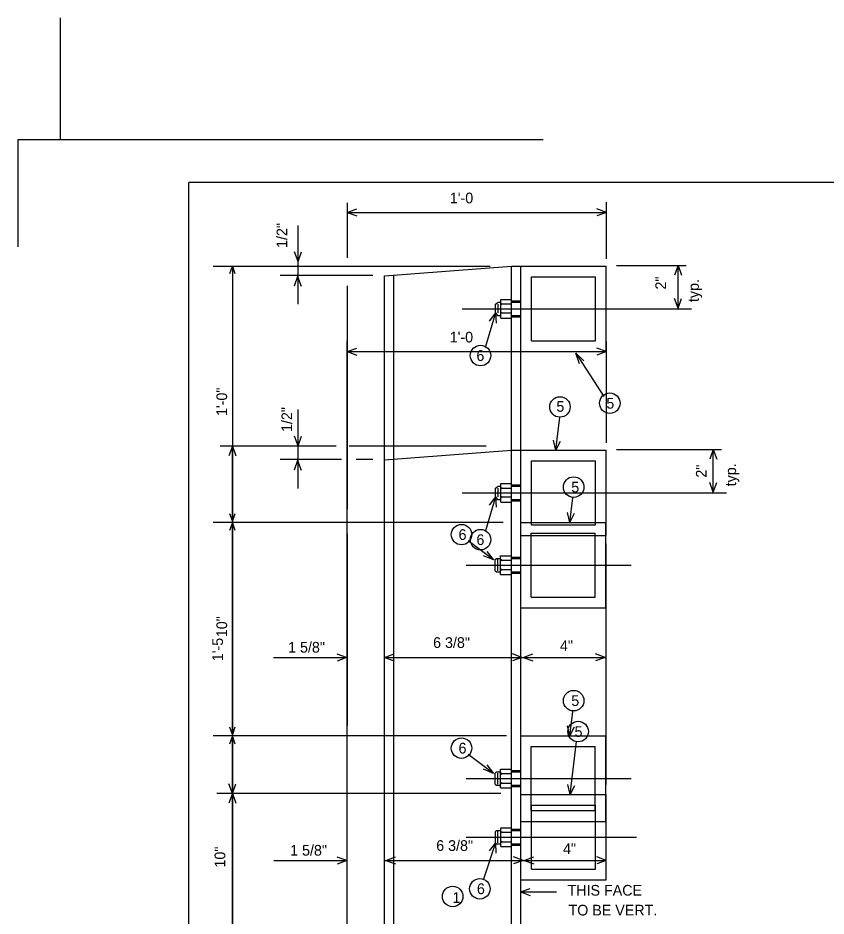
# Model space of a CAD drawing. Extents: x 1509.2 to 1521.3, y 1506 to 1514.6.
# Drawn here: x 1509.587 to 1512.741, y 1511.069 to 1514.573 of the extents above; entities that cross this region are included whole.
import ezdxf

# ---------------------------------------------------------------- set-up
doc = ezdxf.new("R2010")
doc.units = 0
for name, color, linetype in [('Level 1', 7, 'Continuous'), ('Level 2', 7, 'Continuous'), ('Level 3', 7, 'Continuous'), ('Level 4', 7, 'Continuous')]:
    doc.layers.add(name, color=color, linetype=linetype)

msp = doc.modelspace()

# ---------------------------------------------------------------- linework, layer by layer
at = {"layer": 'Level 1'}
for p, q in [((1511.6374, 1514.0975), (1509.5873, 1514.0975)), ((1509.5873, 1514.0975), (1509.5873, 1513.68)), ((1510.2539, 1506.9309), (1510.2539, 1513.9308)), ((1520.7124, 1513.9308), (1510.2539, 1513.9308))]:
    msp.add_line(p, q, dxfattribs=at)
at = {"layer": 'Level 2'}
msp.add_line((1509.7539, 1514.0975), (1509.7539, 1514.573), dxfattribs=at)
at = {"layer": 'Level 3'}
for p, q in [((1510.8717, 1511.5761), (1510.8717, 1513.3132)), ((1511.8837, 1512.9148), (1511.8837, 1513.3111)), ((1510.8717, 1513.271), (1510.9093, 1513.2847)), ((1510.8717, 1513.271), (1510.9093, 1513.2847)), ((1510.8717, 1513.271), (1511.8838, 1513.271)), ((1510.8717, 1513.271), (1510.9093, 1513.2573)), ((1510.8717, 1513.271), (1510.9093, 1513.2573)), ((1511.8838, 1513.271), (1511.8462, 1513.2847)), ((1511.8838, 1513.271), (1511.8462, 1513.2573)), ((1510.6803, 1512.7373), (1510.6803, 1513.0447)), ((1511.6858, 1512.8863), (1511.7023, 1513.0152)), ((1510.6804, 1512.904), (1510.6668, 1512.9416)), ((1510.6804, 1512.904), (1510.6941, 1512.9416)), ((1511.6858, 1512.8863), (1511.677, 1512.9253)), ((1511.6858, 1512.8863), (1511.7041, 1512.9218)), ((1510.8289, 1512.9018), (1510.3763, 1512.9018)), ((1510.4243, 1512.9017), (1510.4106, 1512.8641)), ((1510.4243, 1510.1046), (1510.4243, 1512.9017)), ((1510.4243, 1512.9017), (1510.4379, 1512.8641)), ((1511.4146, 1512.9018), (1510.8798, 1512.9018)), ((1511.0178, 1512.8483), (1511.5127, 1512.8863)), ((1511.5127, 1512.8863), (1511.8824, 1512.8863)), ((1511.5127, 1510.1884), (1511.5127, 1512.8863)), ((1511.5491, 1510.1896), (1511.5491, 1512.8862)), ((1511.8824, 1512.553), (1511.8824, 1512.8863)), ((1511.9228, 1512.8888), (1512.3322, 1512.8888)), ((1512.3007, 1512.8887), (1512.287, 1512.8511)), ((1512.3007, 1512.8887), (1512.287, 1512.8511)), ((1512.3007, 1512.8887), (1512.3143, 1512.8511)), ((1512.3007, 1512.8887), (1512.3143, 1512.8511)), ((1512.3007, 1512.7183), (1512.3007, 1512.8887)), ((1510.8499, 1512.8497), (1510.611, 1512.8497)), ((1510.6786, 1512.8457), (1510.6649, 1512.8081)), ((1510.6786, 1512.8457), (1510.6923, 1512.8081)), ((1510.9715, 1512.8497), (1510.9068, 1512.8497)), ((1511.0178, 1510.1816), (1511.0178, 1512.8483)), ((1511.0543, 1510.1816), (1511.0543, 1512.8483)), ((1511.5908, 1512.8446), (1511.8408, 1512.8446)), ((1511.5908, 1512.5948), (1511.5908, 1512.8446)), ((1511.8408, 1512.5948), (1511.8408, 1512.8446)), ((1511.4502, 1512.7379), (1511.4617, 1512.7459)), ((1511.4502, 1512.7038), (1511.4502, 1512.7379)), ((1511.4617, 1512.7459), (1511.4709, 1512.7459)), ((1511.4617, 1512.7038), (1511.4617, 1512.7379)), ((1511.471, 1512.6834), (1511.471, 1512.7564)), ((1511.471, 1512.7564), (1511.5128, 1512.7564)), ((1511.471, 1512.7386), (1511.4714, 1512.7386)), ((1511.4762, 1512.7386), (1511.5131, 1512.7386)), ((1511.5127, 1512.7459), (1511.5479, 1512.7459)), ((1511.5131, 1512.7512), (1511.5479, 1512.7512)), ((1512.3007, 1512.7225), (1512.287, 1512.7601)), ((1512.3007, 1512.7225), (1512.3143, 1512.7601)), ((1511.3213, 1512.7198), (1512.3528, 1512.7198)), ((1511.4502, 1512.7038), (1511.412, 1512.5721)), ((1511.4502, 1512.7038), (1511.4266, 1512.6715)), ((1511.4502, 1512.7038), (1511.4588, 1512.6938)), ((1511.4502, 1512.7038), (1511.4528, 1512.6639)), ((1511.4588, 1512.6938), (1511.471, 1512.6938)), ((1511.4764, 1512.7038), (1511.5127, 1512.7038)), ((1511.5132, 1512.6938), (1511.5479, 1512.6938)), ((1512.3007, 1512.7196), (1512.3002, 1512.7183)), ((1512.3007, 1512.7196), (1512.3012, 1512.7183)), ((1511.471, 1512.6834), (1511.5127, 1512.6834)), ((1511.5128, 1512.6886), (1511.5479, 1512.6886)), ((1511.5908, 1512.5948), (1511.8408, 1512.5948)), ((1511.5491, 1512.553), (1511.8824, 1512.553)), ((1511.8833, 1511.5824), (1511.8833, 1512.5205)), ((1510.585, 1512.0775), (1510.8713, 1512.0775)), ((1510.8698, 1512.0769), (1510.8323, 1512.0906)), ((1510.8698, 1512.0769), (1510.8323, 1512.0633)), ((1511.0178, 1512.0775), (1511.0553, 1512.0912)), ((1511.0178, 1512.0775), (1511.8787, 1512.0775)), ((1511.0178, 1512.0775), (1511.0553, 1512.0638)), ((1511.5542, 1512.0775), (1511.5166, 1512.0912)), ((1511.5542, 1512.0775), (1511.5166, 1512.0638)), ((1511.5586, 1512.0775), (1511.5962, 1512.0912)), ((1511.5586, 1512.0775), (1511.5962, 1512.0638)), ((1511.8787, 1512.0775), (1511.8411, 1512.0912)), ((1511.8787, 1512.0775), (1511.8411, 1512.0638)), ((1511.7419, 1511.5427), (1511.7665, 1511.7491)), ((1510.4243, 1511.5473), (1510.4106, 1511.5848)), ((1510.4243, 1511.5473), (1510.4379, 1511.5848)), ((1511.7419, 1511.5427), (1511.7328, 1511.5816)), ((1511.7419, 1511.5427), (1511.7599, 1511.5783)), ((1511.471, 1511.5466), (1510.3629, 1511.5466)), ((1510.4243, 1511.5463), (1510.4106, 1511.5088)), ((1510.4243, 1511.5463), (1510.4379, 1511.5088)), ((1511.5498, 1511.5427), (1511.8824, 1511.5427)), ((1511.8824, 1511.2094), (1511.8824, 1511.5427)), ((1510.8717, 1510.0655), (1510.8717, 1511.5101)), ((1511.5908, 1511.501), (1511.8408, 1511.501)), ((1511.5908, 1511.2512), (1511.5908, 1511.501)), ((1511.8408, 1511.2512), (1511.8408, 1511.501)), ((1511.4502, 1511.3978), (1511.4549, 1511.4022)), ((1511.4502, 1511.3543), (1511.4502, 1511.3978)), ((1511.4549, 1511.4022), (1511.4711, 1511.4022)), ((1511.4603, 1511.3543), (1511.4603, 1511.3978)), ((1511.471, 1511.4128), (1511.5123, 1511.4128)), ((1511.471, 1511.3398), (1511.471, 1511.4128)), ((1511.5128, 1511.4074), (1511.5495, 1511.4074)), ((1511.5128, 1511.4022), (1511.5495, 1511.4022)), ((1511.3364, 1511.3762), (1512.0005, 1511.3762)), ((1511.4763, 1511.3958), (1511.5123, 1511.3958)), ((1511.4502, 1511.3543), (1511.4045, 1511.212)), ((1511.4502, 1511.3543), (1511.4257, 1511.3227)), ((1511.4502, 1511.3543), (1511.4552, 1511.3502)), ((1511.4502, 1511.3543), (1511.4517, 1511.3143)), ((1511.4552, 1511.3502), (1511.4706, 1511.3502)), ((1511.471, 1511.3398), (1511.5128, 1511.3398)), ((1511.4763, 1511.3584), (1511.5128, 1511.3584)), ((1511.5128, 1511.3502), (1511.5495, 1511.3502)), ((1511.5128, 1511.345), (1511.5495, 1511.345)), ((1511.5908, 1511.2512), (1511.8408, 1511.2512)), ((1511.5483, 1511.2094), (1511.8824, 1511.2094))]:
    msp.add_line(p, q, dxfattribs=at)
for centre in [(1511.7023, 1513.0552), (1511.3924, 1512.5373), (1511.7731, 1511.7884), (1511.3897, 1511.1749)]:
    msp.add_circle(centre, 0.04, dxfattribs=at)
for centre, radius, start, end in [((1511.478, 1512.7468), 0.0083, 212.6971, 259.113), ((1511.4765, 1512.7324), 0.00576, 91.1935, 163.9436), ((1511.478, 1512.712), 0.0083, 212.6971, 259.113), ((1511.4765, 1512.6981), 0.00576, 91.1935, 163.9436), ((1511.4801, 1511.4061), 0.011, 213.851, 249.2744), ((1511.4786, 1511.3875), 0.00865, 106.0183, 151.9637), ((1511.4801, 1511.3687), 0.011, 213.851, 249.2744), ((1511.4786, 1511.3501), 0.00865, 106.0183, 151.9637)]:
    msp.add_arc(centre, radius, start, end, dxfattribs=at)
at = {"layer": 'Level 4'}
for p, q in [((1510.8717, 1513.8515), (1510.8717, 1513.6368)), ((1511.8837, 1513.6332), (1511.8837, 1513.8542)), ((1510.8717, 1513.8141), (1510.9093, 1513.8278)), ((1510.8717, 1513.8141), (1510.9093, 1513.8278)), ((1511.8838, 1513.8141), (1511.8462, 1513.8278)), ((1510.8717, 1513.8141), (1511.8838, 1513.8141)), ((1510.8717, 1513.8141), (1510.9093, 1513.8004)), ((1510.8717, 1513.8141), (1510.9093, 1513.8004)), ((1511.8838, 1513.8141), (1511.8462, 1513.8004)), ((1510.6803, 1513.4557), (1510.6803, 1513.763)), ((1510.6804, 1513.6223), (1510.6668, 1513.6599)), ((1510.6804, 1513.6223), (1510.6941, 1513.6599)), ((1510.3492, 1513.6046), (1511.4306, 1513.6046)), ((1510.4243, 1513.6046), (1510.4243, 1512.4367)), ((1511.0178, 1513.5667), (1511.5127, 1513.6046)), ((1511.5127, 1513.6046), (1511.8824, 1513.6046)), ((1511.5127, 1510.1884), (1511.5127, 1513.6046)), ((1511.5491, 1510.1896), (1511.5491, 1513.6046)), ((1511.8824, 1513.2713), (1511.8824, 1513.6046)), ((1511.9228, 1513.6071), (1512.195, 1513.6071)), ((1512.1635, 1513.607), (1512.1498, 1513.5694)), ((1512.1635, 1513.607), (1512.1498, 1513.5694)), ((1512.1635, 1513.4348), (1512.1635, 1513.6071)), ((1512.1635, 1513.607), (1512.1772, 1513.5694)), ((1512.1635, 1513.607), (1512.1772, 1513.5694)), ((1511.0543, 1510.1816), (1511.0543, 1513.5695)), ((1510.9715, 1513.568), (1510.611, 1513.568)), ((1510.6786, 1513.564), (1510.6649, 1513.5264)), ((1510.6786, 1513.564), (1510.6923, 1513.5264)), ((1511.0178, 1510.1816), (1511.0178, 1513.5667)), ((1511.5908, 1513.5629), (1511.8408, 1513.5629)), ((1511.5908, 1513.3131), (1511.5908, 1513.5629)), ((1511.8408, 1513.3131), (1511.8408, 1513.5629)), ((1510.8717, 1513.5273), (1510.8717, 1512.6558)), ((1511.4502, 1513.4563), (1511.4617, 1513.4643)), ((1511.4617, 1513.4643), (1511.4709, 1513.4643)), ((1511.471, 1513.4018), (1511.471, 1513.4748)), ((1511.471, 1513.4748), (1511.5128, 1513.4748)), ((1511.5127, 1513.4643), (1511.5479, 1513.4643)), ((1511.5131, 1513.4695), (1511.5479, 1513.4695)), ((1512.1635, 1513.4408), (1512.1498, 1513.4784)), ((1512.1635, 1513.4408), (1512.1772, 1513.4784)), ((1511.3213, 1513.4381), (1512.2156, 1513.4381)), ((1511.4502, 1513.4222), (1511.4502, 1513.4563)), ((1511.4617, 1513.4222), (1511.4617, 1513.4563)), ((1511.471, 1513.4569), (1511.4714, 1513.4569)), ((1511.4762, 1513.4569), (1511.5131, 1513.4569)), ((1512.1635, 1513.4379), (1512.1623, 1513.4348)), ((1512.1635, 1513.4379), (1512.1647, 1513.4348)), ((1511.4502, 1513.4222), (1511.412, 1513.2904)), ((1511.4502, 1513.4222), (1511.4266, 1513.3898)), ((1511.4502, 1513.4222), (1511.4588, 1513.4121)), ((1511.4502, 1513.4222), (1511.4528, 1513.3823)), ((1511.4588, 1513.4121), (1511.471, 1513.4121)), ((1511.471, 1513.4018), (1511.5127, 1513.4018)), ((1511.4764, 1513.4222), (1511.5127, 1513.4222)), ((1511.5128, 1513.4069), (1511.5479, 1513.4069)), ((1511.5132, 1513.4121), (1511.5479, 1513.4121)), ((1511.5908, 1513.3131), (1511.8408, 1513.3131)), ((1511.5491, 1513.2713), (1511.8824, 1513.2713)), ((1511.7641, 1513.2644), (1511.874, 1513.0955)), ((1511.7412, 1512.6046), (1511.7525, 1512.7)), ((1511.7412, 1512.6046), (1511.732, 1512.6435)), ((1511.7412, 1512.6046), (1511.7592, 1512.6403)), ((1511.481, 1512.6046), (1510.3492, 1512.6046)), ((1511.5491, 1512.6046), (1511.8817, 1512.6046)), ((1511.8817, 1512.2713), (1511.8817, 1512.6046)), ((1510.8717, 1512.5602), (1510.8717, 1511.8118)), ((1511.5901, 1512.5629), (1511.84, 1512.5629)), ((1511.5901, 1512.3131), (1511.5901, 1512.5629)), ((1511.84, 1512.3131), (1511.84, 1512.5629)), ((1511.4436, 1512.458), (1511.3438, 1512.5328)), ((1511.4494, 1512.4597), (1511.4542, 1512.4641)), ((1511.4494, 1512.4162), (1511.4494, 1512.4597)), ((1511.4542, 1512.4641), (1511.4703, 1512.4641)), ((1511.4596, 1512.4162), (1511.4596, 1512.4597)), ((1511.4703, 1512.4017), (1511.4703, 1512.4748)), ((1511.4703, 1512.4747), (1511.5116, 1512.4747)), ((1511.4755, 1512.4578), (1511.5116, 1512.4578)), ((1511.5121, 1512.4693), (1511.5488, 1512.4693)), ((1511.5121, 1512.4641), (1511.5488, 1512.4641)), ((1510.4243, 1512.4367), (1510.4243, 1510.9438)), ((1511.3357, 1512.4381), (1511.9798, 1512.4381)), ((1511.4494, 1512.4162), (1511.4544, 1512.4121)), ((1511.4755, 1512.4203), (1511.5121, 1512.4203)), ((1511.4544, 1512.4121), (1511.4698, 1512.4121)), ((1511.4703, 1512.4017), (1511.5121, 1512.4017)), ((1511.5121, 1512.4121), (1511.5488, 1512.4121)), ((1511.5121, 1512.4069), (1511.5488, 1512.4069)), ((1511.5901, 1512.3131), (1511.84, 1512.3131)), ((1511.5475, 1512.2713), (1511.8817, 1512.2713)), ((1511.7412, 1511.7713), (1511.7525, 1511.8667)), ((1511.7412, 1511.7713), (1511.732, 1511.8102)), ((1511.7412, 1511.7713), (1511.7592, 1511.8069)), ((1511.4935, 1511.7713), (1510.3492, 1511.7713)), ((1511.5491, 1511.7713), (1511.8817, 1511.7713)), ((1511.8817, 1511.438), (1511.8817, 1511.7713)), ((1510.8717, 1510.9678), (1510.8717, 1511.7411)), ((1511.5901, 1511.7296), (1511.84, 1511.7296)), ((1511.5901, 1511.4798), (1511.5901, 1511.7296)), ((1511.84, 1511.4798), (1511.84, 1511.7296)), ((1511.4436, 1511.6247), (1511.3438, 1511.6995)), ((1511.4494, 1511.6263), (1511.4542, 1511.6308)), ((1511.4494, 1511.5828), (1511.4494, 1511.6263)), ((1511.4542, 1511.6308), (1511.4703, 1511.6308)), ((1511.4596, 1511.5828), (1511.4596, 1511.6263)), ((1511.4703, 1511.5683), (1511.4703, 1511.6414)), ((1511.4703, 1511.6413), (1511.5116, 1511.6413)), ((1511.4755, 1511.6244), (1511.5116, 1511.6244)), ((1511.5121, 1511.636), (1511.5488, 1511.636)), ((1511.5121, 1511.6308), (1511.5488, 1511.6308)), ((1511.3357, 1511.6048), (1511.9798, 1511.6048)), ((1511.4494, 1511.5828), (1511.4544, 1511.5788)), ((1511.4544, 1511.5788), (1511.4698, 1511.5788)), ((1511.4755, 1511.587), (1511.5121, 1511.587)), ((1511.5121, 1511.5788), (1511.5488, 1511.5788)), ((1511.5121, 1511.5736), (1511.5488, 1511.5736)), ((1511.4703, 1511.5683), (1511.5121, 1511.5683)), ((1511.5901, 1511.4798), (1511.84, 1511.4798)), ((1511.5475, 1511.438), (1511.8817, 1511.438)), ((1511.8833, 1511.2285), (1511.8833, 1511.3889)), ((1510.8703, 1511.2847), (1510.8328, 1511.2983)), ((1511.0224, 1511.2854), (1511.06, 1511.2991)), ((1511.5588, 1511.2854), (1511.5213, 1511.2991)), ((1511.5633, 1511.2854), (1511.6008, 1511.2991)), ((1511.8833, 1511.2854), (1511.8458, 1511.2991)), ((1510.5855, 1511.2853), (1510.8718, 1511.2853)), ((1510.8703, 1511.2847), (1510.8328, 1511.271)), ((1511.0188, 1511.2854), (1511.8833, 1511.2854)), ((1511.0224, 1511.2854), (1511.06, 1511.2718)), ((1511.5588, 1511.2854), (1511.5213, 1511.2718)), ((1511.5633, 1511.2854), (1511.6008, 1511.2718)), ((1511.8833, 1511.2854), (1511.8458, 1511.2718)), ((1511.5483, 1511.1627), (1511.5859, 1511.1763)), ((1511.5483, 1511.1627), (1511.6888, 1511.1627)), ((1511.5483, 1511.1627), (1511.5859, 1511.149))]:
    msp.add_line(p, q, dxfattribs=at)
for points in [[(1510.4145, 1513.5764), (1510.4243, 1513.6046), (1510.434, 1513.5764)], [(1511.7781, 1513.2238), (1511.7641, 1513.2644), (1511.7955, 1513.2352)], [(1510.434, 1512.6386), (1510.4243, 1512.6104), (1510.4145, 1512.6386)], [(1510.4145, 1512.5739), (1510.4243, 1512.6021), (1510.434, 1512.5739)], [(1511.4165, 1512.4913), (1511.4436, 1512.458), (1511.404, 1512.4747)], [(1510.434, 1511.8053), (1510.4243, 1511.7771), (1510.4145, 1511.8053)], [(1510.4145, 1511.7406), (1510.4243, 1511.7688), (1510.434, 1511.7406)], [(1511.4165, 1511.658), (1511.4436, 1511.6247), (1511.404, 1511.6413)]]:
    msp.add_lwpolyline(points, dxfattribs=at)
for centre in [(1511.3924, 1513.2556), (1511.8968, 1513.0698), (1511.7557, 1512.7423), (1511.3183, 1512.557), (1511.7557, 1511.9089), (1511.3183, 1511.7237), (1511.2838, 1511.1449)]:
    msp.add_circle(centre, 0.04, dxfattribs=at)
for centre, radius, start, end in [((1511.478, 1513.4651), 0.0083, 212.6971, 259.113), ((1511.4765, 1513.4507), 0.00576, 91.1935, 163.9436), ((1511.478, 1513.4303), 0.0083, 212.6971, 259.113), ((1511.4765, 1513.4164), 0.00576, 91.1935, 163.9436), ((1511.4794, 1512.4681), 0.011, 213.851, 249.2744), ((1511.4779, 1512.4494), 0.00865, 106.0183, 151.9637), ((1511.4794, 1512.4306), 0.011, 213.851, 249.2744), ((1511.4779, 1512.412), 0.00865, 106.0183, 151.9637), ((1511.4794, 1511.6347), 0.011, 213.851, 249.2744), ((1511.4779, 1511.6161), 0.00865, 106.0183, 151.9637), ((1511.4794, 1511.5973), 0.011, 213.851, 249.2744), ((1511.4779, 1511.5787), 0.00865, 106.0183, 151.9637)]:
    msp.add_arc(centre, radius, start, end, dxfattribs=at)

# ---------------------------------------------------------------- texts
at = {"layer": 'Level 3'}
for s, height, rotation, p in [("1'-0", 0.04167, 360, (1511.2722, 1513.3067)), ('1/2"', 0.04167, 90, (1510.6573, 1512.9573)), ('5', 0.0417, 0, (1511.6885, 1513.0364)), ('2"', 0.04167, 90, (1512.2746, 1512.7793)), ('typ.', 0.04167, 90, (1512.3897, 1512.7453)), ('6', 0.0417, 0, (1511.3765, 1512.5164)), ("1'-5", 0.04167, 90, (1510.3874, 1512.063)), ('1 5/8"', 0.04167, 0, (1510.6415, 1512.0966)), ('6 3/8"', 0.04167, 360, (1511.2073, 1512.1149)), ('4"', 0.04167, 0, (1511.7024, 1512.1024)), ('5', 0.0417, 0, (1511.7593, 1511.7676)), ('6', 0.0417, 0, (1511.3783, 1511.1541))]:
    msp.add_text(s, height=height, rotation=rotation, dxfattribs=at).set_placement(p)
at = {"layer": 'Level 4'}
for s, height, rotation, p in [("1'-0", 0.04167, 360, (1511.2727, 1513.8498)), ('1/2"', 0.04167, 90, (1510.6382, 1513.6756)), ('2"', 0.04167, 90, (1512.1162, 1513.5133)), ('typ.', 0.04167, 90, (1512.2444, 1513.4643)), ('6', 0.0417, 0, (1511.3763, 1513.2348)), ('1\'-0"', 0.04167, 90, (1510.4034, 1513.0198)), ('5', 0.0417, 0, (1511.8833, 1513.0484)), ('5', 0.0417, 0, (1511.7465, 1512.7214)), ('6', 0.0417, 0, (1511.3066, 1512.5362)), ('10"', 0.04167, 90, (1510.4034, 1512.1567)), ('5', 0.0417, 0, (1511.7465, 1511.8881)), ('6', 0.0417, 0, (1511.3066, 1511.7028)), ('6 3/8"', 0.04167, 360, (1511.2195, 1511.3228)), ('10"', 0.04167, 90, (1510.3963, 1511.2578)), ('1 5/8"', 0.04167, 0, (1510.6494, 1511.3043)), ('4"', 0.04167, 0, (1511.7144, 1511.3103)), ('THIS FACE', 0.04167, 0, (1511.7318, 1511.1483)), ('1', 0.0417, 0, (1511.2832, 1511.12)), ('TO BE VERT.', 0.041667, 0, (1511.7356, 1511.0707))]:
    msp.add_text(s, height=height, rotation=rotation, dxfattribs=at).set_placement(p)

doc.saveas('drawing.dxf')
